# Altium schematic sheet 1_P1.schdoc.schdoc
size 309 x 223 mm; Symbol: Sheet-Symbol_A4; Device: Sheet-Symbol_A4; @Page Name: P1; @Create Date: 2023-06-26; @Page Count: 1; @Page No: 1; @Project Name: New Project_2023-06-26_22-31-54; @Schematic Name: Schematic1; @Update Date: 2023-11-04; Company: 嘉立创EDA; Page Size: A4; Version: V1.0
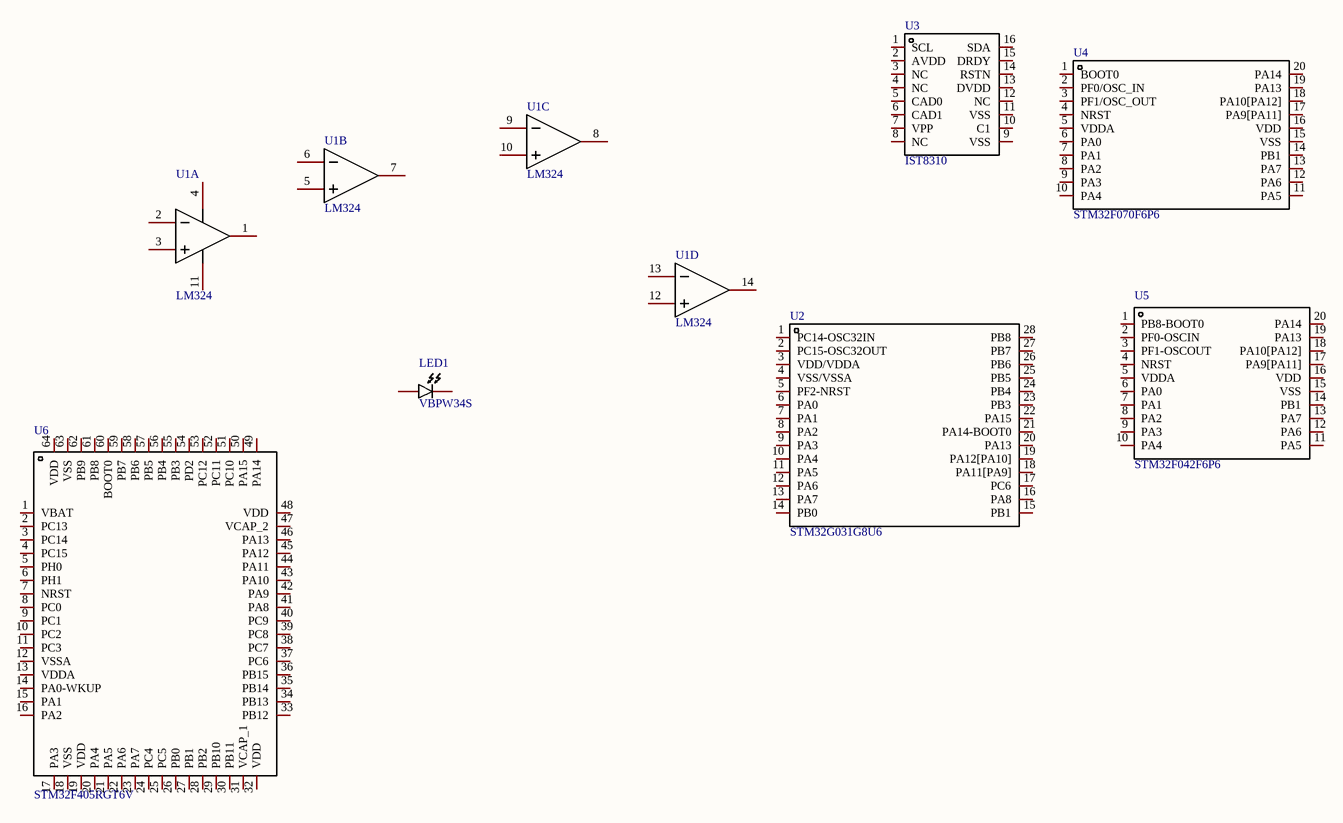
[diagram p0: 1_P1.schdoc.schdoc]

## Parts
LED1  VBPW34S  [SENSOR-SMD_L4.4-W3.9]
U1  LM324  [SOP-14_L8.6-W3.9-P1.27-LS6.0-BL]  (parts A,B,C,D of 4)
U2  STM32G031G8U6  [UFQFPN-28_L4.0-W4.0-P0.50-BL]
U3  IST8310  [LGA-16_L3.0-W3.0-P0.5-BL]
U4  STM32F070F6P6  [TSSOP-20_L6.5-W4.4-P0.65-LS6.4-BL]
U5  STM32F042F6P6  [TSSOP-20_L6.5-W4.4-P0.65-LS6.4-BL]
U6  STM32F405RGT6V  [LQFP-64_L10.0-W10.0-P0.50-LS12.0-BL]

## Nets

Not connected (* = marked no-connect by the designer): LED1 1(A) 2(C); U1 1(VOUTA) 2(VINA-) 3(VINA+) 4(VDD) 5(VINB+) 6(VINB-) 7(VOUTB) 8(VOUTC) 9(VINC-) 10(VINC+) 11(VSS) 12(VIND+) 13(VIND-) 14(VOUTD); U2 1(PC14-OSC32IN) 2(PC15-OSC32OUT) 3(VDD/VDDA) 4(VSS/VSSA) 5(PF2-NRST) 6(PA0) 7(PA1) 8(PA2) 9(PA3) 10(PA4) 11(PA5) 12(PA6) 13(PA7) 14(PB0) 15(PB1) 16(PA8) 17(PC6) 18(PA11[PA9]) 19(PA12[PA10]) 20(PA13) 21(PA14-BOOT0) 22(PA15) 23(PB3) 24(PB4) 25(PB5) 26(PB6) 27(PB7) 28(PB8); U3 1(SCL) 2(AVDD) 3(NC) 4(NC) 5(CAD0) 6(CAD1) 7(VPP) 8(NC) 9(VSS) 10(C1) 11(VSS) 12(NC) 13(DVDD) 14(RSTN) 15(DRDY) 16(SDA); U4 1(BOOT0) 2(PF0/OSC_IN) 3(PF1/OSC_OUT) 4(NRST) 5(VDDA) 6(PA0) 7(PA1) 8(PA2) 9(PA3) 10(PA4) 11(PA5) 12(PA6) 13(PA7) 14(PB1) 15(VSS) 16(VDD) 17(PA9[PA11]) 18(PA10[PA12]) 19(PA13) 20(PA14); U5 1(PB8-BOOT0) 2(PF0-OSCIN) 3(PF1-OSCOUT) 4(NRST) 5(VDDA) 6(PA0) 7(PA1) 8(PA2) 9(PA3) 10(PA4) 11(PA5) 12(PA6) 13(PA7) 14(PB1) 15(VSS) 16(VDD) 17(PA9[PA11]) 18(PA10[PA12]) 19(PA13) 20(PA14); U6 1(VBAT) 2(PC13) 3(PC14) 4(PC15) 5(PH0) 6(PH1) 7(NRST) 8(PC0) 9(PC1) 10(PC2) 11(PC3) 12(VSSA) 13(VDDA) 14(PA0-WKUP) 15(PA1) 16(PA2) 17(PA3) 18(VSS) 19(VDD) 20(PA4) 21(PA5) 22(PA6) 23(PA7) 24(PC4) 25(PC5) 26(PB0) 27(PB1) 28(PB2) 29(PB10) 30(PB11) 31(VCAP_1) 32(VDD) 33(PB12) 34(PB13) 35(PB14) 36(PB15) 37(PC6) 38(PC7) 39(PC8) 40(PC9) 41(PA8) 42(PA9) 43(PA10) 44(PA11) 45(PA12) 46(PA13) 47(VCAP_2) 48(VDD) 49(PA14) 50(PA15) 51(PC10) 52(PC11) 53(PC12) 54(PD2) 55(PB3) 56(PB4) 57(PB5) 58(PB6) 59(PB7) 60(BOOT0) 61(PB8) 62(PB9) 63(VSS) 64(VDD)

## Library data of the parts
LED1 = VBPW34S: 峰值波长:940nm;响应范围:430nm~1100nm;反向电压:60V;暗电流:2nA;接收角:-;工作温度:-40℃~+100℃;; Manufacturer: VISHAY(威世); Add into BOM: yes; Peak  Wavelength: 940nm; DC Reverse Voltage: 60V; Current Dark: 2nA
U1 = LM324: Manufacturer: CJ(江苏长电/长晶); Symbol: LM324_C2829425; Add into BOM: yes
U2 = STM32G031G8U6: CPU内核:ARM-M系列;CPU最大主频:64MHz;程序存储容量:64KB;程序存储器类型:FLASH;RAM总容量:-;GPIO端口数量:26;; Manufacturer: ST(意法半导体); Add into BOM: yes; CPU Maximum Speed: 64MHz; Operating Voltage Range: 1.7V~3.6V; Program Storage Size: 64KB; Program Memory Type: FLASH; GPIO Ports Number: 26; ADC (Bit): 12bit; Watchdog: 有
U3 = IST8310: Add into BOM: yes
U4 = STM32F070F6P6: CPU内核:ARM Cortex-M0;CPU最大主频:48MHz;工作电压范围:2.4V~3.6V;程序存储容量:32KB;程序存储器类型:FLASH;RAM总容量:6KB;GPIO端口数量:15;; Manufacturer: ST(意法半导体); Add into BOM: yes; CPU Maximum Speed: 48MHz; Program Storage Size: 32KB; Program Memory Type: FLASH; RAM Size: 6KB; GPIO Ports Number: 15; ADC (Bit): 12bit; Peripheral/Function: DMA；PWM; Internal Oscillator: 有
U5 = STM32F042F6P6: CPU内核:ARM Cortex-M0;CPU最大主频:48MHz;工作电压范围:1.65V~3.6V;程序存储容量:32KB;程序存储器类型:FLASH;RAM总容量:6KB;GPIO端口数量:16;; Manufacturer: ST(意法半导体); Add into BOM: yes; CPU Maximum Speed: 48MHz; Program Storage Size: 32KB; Program Memory Type: FLASH; RAM Size: 6KB; GPIO Ports Number: 16; ADC (Bit): 12bit; Universal Serial Bus: 有; Peripheral/Function: DMA；看门狗；看门狗
U6 = STM32F405RGT6V: Manufacturer: ST(意法半导体); Add into BOM: yes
